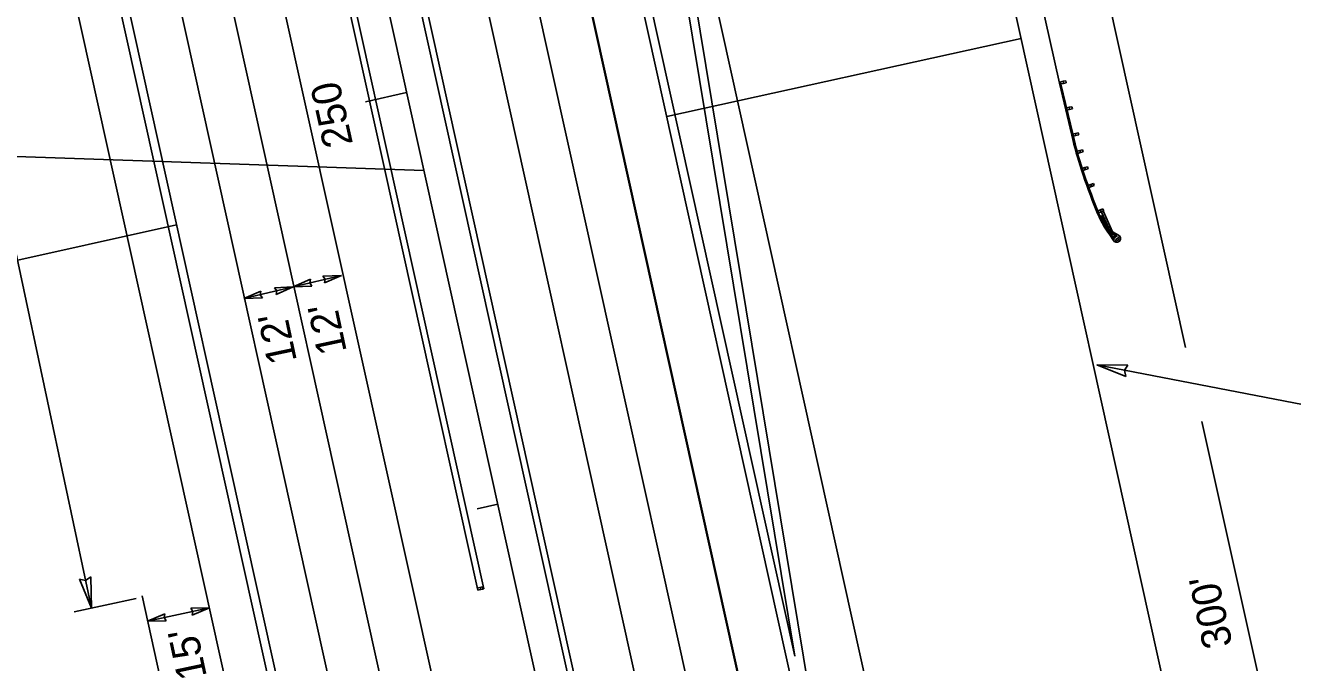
# Model space of a CAD drawing. Extents: x 578088 to 579220, y 1508751 to 1510398.
# Drawn here: x 578333.4 to 578633.8, y 1509907.9 to 1510059 of the extents above; entities that cross this region are included whole.
import ezdxf

# ---------------------------------------------------------------- set-up
doc = ezdxf.new("R2010")
doc.units = 0
for name, color, linetype in [('1', 7, 'Continuous'), ('18', 7, 'Continuous'), ('2', 7, 'Continuous'), ('28', 7, 'Continuous'), ('41', 7, 'Continuous'), ('46', 7, 'Continuous'), ('52', 7, 'Continuous')]:
    doc.layers.add(name, color=color, linetype=linetype)

msp = doc.modelspace()

# ---------------------------------------------------------------- linework, layer by layer
at = {"layer": '1'}
for p, q in [((578639.69, 1509066.69), (578362.17, 1510321.74)), ((578559.88, 1509205.29), (578315.3, 1510311.37))]:
    msp.add_line(p, q, dxfattribs=at)
at = {"layer": '18'}
for p, q in [((578612.63, 1509860.67), (578504, 1510351.92)), ((578545.42, 1509845.81), (578436.79, 1510337.06)), ((578516.77, 1509839.48), (578408.15, 1510330.73)), ((578471.12, 1509495.56), (578291.87, 1510306.19)), ((578415.3, 1510242.58), (578497.77, 1509869.64)), ((578659.48, 1508810.53), (578375.62, 1510094.27)), ((578432.7, 1509599.82), (578361.09, 1509923.69))]:
    msp.add_line(p, q, dxfattribs=at)
at = {"layer": '2'}
for p, q in [((578528.65, 1509842.11), (578420.03, 1510333.36)), ((578515.82, 1509909.43), (578421.98, 1510333.79)), ((578516.94, 1509839.51), (578408.31, 1510330.77)), ((578493.5, 1509834.33), (578384.88, 1510325.58)), ((578482.83, 1509498.15), (578303.59, 1510308.78)), ((578480.88, 1509497.72), (578301.64, 1510308.35)), ((578523.79, 1509873.37), (578484.67, 1510110.52)), ((578515.82, 1509909.43), (578482.71, 1510110.09)), ((578569.45, 1510055.96), (578485.47, 1510037.39)), ((578369.28, 1510011.7), (578294.1, 1509995.07))]:
    msp.add_line(p, q, dxfattribs=at)
at = {"layer": '28'}
for p, q in [((578423.79, 1510043.1), (578414.02, 1510040.94)), ((578445.38, 1509945.46), (578440.49, 1509944.38))]:
    msp.add_line(p, q, dxfattribs=at)
at = {"layer": '41'}
for p, q in [((578612.63, 1509860.67), (578504, 1510351.91)), ((578612.63, 1509860.67), (578504, 1510351.91)), ((578612.63, 1509860.67), (578504, 1510351.91)), ((578671.2, 1508813.02), (578338.64, 1510317))]:
    msp.add_line(p, q, dxfattribs=at)
msp.add_arc((580335.96, 1510415.53), 2083.48, 192.46859, 200.71859, dxfattribs=at)
at = {"layer": '46'}
for p, q in [((578369.74, 1510322.24), (578478.37, 1509830.99)), ((578371.21, 1510322.56), (578479.83, 1509831.31)), ((578440.67, 1509925.07), (578353.63, 1510318.68)), ((578442.13, 1509925.39), (578355.1, 1510319)), ((578578.52, 1510045.32), (578519.21, 1510313.84)), ((578578.52, 1510045.32), (578581.48, 1510032.96)), ((578579.39, 1510045.77), (578578.74, 1510045.62)), ((578578.74, 1510045.62), (578578.85, 1510045.14)), ((578578.79, 1510045.38), (578581.75, 1510033.03)), ((578578.85, 1510045.14), (578579.5, 1510045.28)), ((578580.04, 1510045.91), (578579.39, 1510045.77)), ((578579.39, 1510045.77), (578579.5, 1510045.28)), ((578579.5, 1510045.28), (578580.15, 1510045.42)), ((578580.15, 1510045.42), (578580.04, 1510045.91)), ((578580.84, 1510039.6), (578580.19, 1510039.44)), ((578580.19, 1510039.44), (578580.31, 1510038.96)), ((578580.31, 1510038.96), (578580.95, 1510039.11)), ((578581.48, 1510039.75), (578580.84, 1510039.6)), ((578580.84, 1510039.6), (578580.95, 1510039.11)), ((578580.95, 1510039.11), (578581.6, 1510039.27)), ((578581.6, 1510039.27), (578581.48, 1510039.75)), ((578582.34, 1510033.42), (578581.69, 1510033.27)), ((578581.69, 1510033.27), (578581.81, 1510032.78)), ((578581.81, 1510032.78), (578582.45, 1510032.94)), ((578582.99, 1510033.57), (578582.34, 1510033.42)), ((578582.34, 1510033.42), (578582.45, 1510032.94)), ((578582.45, 1510032.94), (578583.1, 1510033.09)), ((578583.1, 1510033.09), (578582.99, 1510033.57)), ((578583.35, 1510029.34), (578582.71, 1510029.16)), ((578582.71, 1510029.16), (578582.84, 1510028.68)), ((578583.99, 1510029.52), (578583.35, 1510029.34)), ((578583.35, 1510029.34), (578583.49, 1510028.86)), ((578583.49, 1510028.86), (578584.13, 1510029.04)), ((578584.13, 1510029.04), (578583.99, 1510029.52)), ((578582.84, 1510028.68), (578583.49, 1510028.86)), ((578584.57, 1510025.3), (578583.94, 1510025.09)), ((578583.94, 1510025.09), (578584.09, 1510024.62)), ((578584.09, 1510024.62), (578584.73, 1510024.83)), ((578585.2, 1510025.52), (578584.57, 1510025.3)), ((578584.57, 1510025.3), (578584.73, 1510024.83)), ((578584.73, 1510024.83), (578585.36, 1510025.04)), ((578585.36, 1510025.04), (578585.2, 1510025.52)), ((578585.97, 1510021.3), (578585.35, 1510021.07)), ((578585.35, 1510021.07), (578585.52, 1510020.6)), ((578585.52, 1510020.6), (578586.15, 1510020.83)), ((578586.6, 1510021.53), (578585.97, 1510021.3)), ((578585.97, 1510021.3), (578586.15, 1510020.83)), ((578586.15, 1510020.83), (578586.77, 1510021.06)), ((578586.77, 1510021.06), (578586.6, 1510021.53)), ((578587.62, 1510015.05), (578588.81, 1510015.51)), ((578587.79, 1510014.61), (578588.96, 1510015.07)), ((578588.23, 1510015.27), (578588.21, 1510015.27)), ((578588.22, 1510015.28), (578588.39, 1510014.85)), ((578588.38, 1510014.83), (578588.37, 1510014.84)), ((578588.96, 1510015.06), (578588.38, 1510014.83)), ((578590.24, 1510010.9), (578588.45, 1510014.86)), ((578588.81, 1510015.51), (578588.97, 1510015.1)), ((578588.83, 1510015.51), (578588.82, 1510015.5)), ((578588.83, 1510015.51), (578588.99, 1510015.11)), ((578591.14, 1510010.05), (578588.92, 1510015.04)), ((578588.1, 1510013.57), (578588.59, 1510013.8)), ((578588.1, 1510013.57), (578588.68, 1510012.35)), ((578588.56, 1510013.82), (578588.33, 1510013.71)), ((578588.33, 1510013.8), (578588.36, 1510013.74)), ((578588.33, 1510013.71), (578588.34, 1510013.68)), ((578588.46, 1510013.87), (578588.35, 1510013.82)), ((578588.36, 1510013.86), (578588.35, 1510013.85)), ((578588.35, 1510013.85), (578588.36, 1510013.83)), ((578588.53, 1510013.82), (578588.35, 1510013.73)), ((578588.35, 1510013.73), (578588.35, 1510013.72)), ((578588.42, 1510013.89), (578588.36, 1510013.86)), ((578588.38, 1510013.82), (578588.41, 1510013.76)), ((578588.43, 1510013.89), (578588.42, 1510013.89)), ((578588.43, 1510013.89), (578588.44, 1510013.87)), ((578588.44, 1510013.85), (578588.47, 1510013.79)), ((578588.48, 1510013.88), (578588.51, 1510013.81)), ((578588.53, 1510013.81), (578588.53, 1510013.82)), ((578588.57, 1510013.79), (578588.56, 1510013.82)), ((578588.59, 1510013.8), (578589.18, 1510012.59)), ((578588.68, 1510012.35), (578589.18, 1510012.59)), ((578589.03, 1510012.52), (578590.59, 1510010.28)), ((578589.08, 1510012.54), (578590.7, 1510010.24)), ((578589.97, 1510010.61), (578589.96, 1510010.61)), ((578589.97, 1510010.61), (578590.07, 1510010.44)), ((578589.99, 1510010.57), (578590.03, 1510010.59)), ((578590.05, 1510010.57), (578590.01, 1510010.55)), ((578590.07, 1510010.53), (578590.04, 1510010.51)), ((578590.05, 1510010.59), (578590.09, 1510010.52)), ((578590.09, 1510010.5), (578590.05, 1510010.48)), ((578590.06, 1510010.57), (578590.08, 1510010.59)), ((578591.83, 1510009.34), (578590.07, 1510010.44)), ((578590.09, 1510010.58), (578590.08, 1510010.59)), ((578590.1, 1510010.55), (578590.08, 1510010.54)), ((578590.09, 1510010.58), (578590.1, 1510010.56)), ((578590.1, 1510010.56), (578590.1, 1510010.55)), ((578590.48, 1510010.32), (578590.36, 1510010.61)), ((578590.52, 1510010.3), (578590.45, 1510010.48)), ((578590.46, 1510009.33), (578590.53, 1510009.7)), ((578590.46, 1510009.33), (578591.36, 1510008.02)), ((578590.47, 1510009.33), (578590.54, 1510009.7)), ((578590.7, 1510009.49), (578590.47, 1510009.33)), ((578590.47, 1510009.33), (578591.36, 1510008.03)), ((578590.53, 1510010.3), (578590.52, 1510010.31)), ((578590.53, 1510009.7), (578590.54, 1510009.7)), ((578590.91, 1510009.3), (578590.56, 1510010.13)), ((578590.65, 1510009.24), (578590.64, 1510009.26)), ((578590.7, 1510009.49), (578591.25, 1510008.68)), ((578590.7, 1510009.3), (578590.71, 1510009.29)), ((578590.8, 1510009.98), (578590.98, 1510009.72)), ((578591.11, 1510009.44), (578590.85, 1510009.26)), ((578591.39, 1510009.61), (578590.86, 1510009.25)), ((578590.86, 1510009.25), (578591.12, 1510008.86)), ((578591.05, 1510008.64), (578590.9, 1510008.86)), ((578590.94, 1510009.89), (578591.04, 1510009.76)), ((578590.96, 1510008.9), (578591.1, 1510008.69)), ((578591.05, 1510009.76), (578590.98, 1510009.71)), ((578591.11, 1510009.52), (578590.98, 1510009.71)), ((578591.02, 1510009.85), (578591.13, 1510010.05)), ((578591.18, 1510009.57), (578591.05, 1510009.76)), ((578591.08, 1510009.48), (578591.12, 1510009.43)), ((578591.2, 1510009.58), (578591.09, 1510009.51)), ((578591.12, 1510009.51), (578591.16, 1510009.45)), ((578591.12, 1510008.86), (578591.65, 1510009.22)), ((578591.13, 1510010.06), (578592.51, 1510009.27)), ((578591.13, 1510010.05), (578592.5, 1510009.26)), ((578591.17, 1510008.8), (578591.69, 1510009.16)), ((578591.18, 1510009.82), (578591.2, 1510009.81)), ((578591.19, 1510009.56), (578591.23, 1510009.5)), ((578591.23, 1510009.88), (578591.22, 1510009.89)), ((578591.22, 1510009.58), (578591.26, 1510009.52)), ((578591.38, 1510009.62), (578591.25, 1510009.53)), ((578591.25, 1510008.68), (578591.35, 1510008.04)), ((578591.33, 1510009.59), (578591.3, 1510009.68)), ((578591.38, 1510009.62), (578591.5, 1510009.83)), ((578591.69, 1510009.16), (578591.39, 1510009.61)), ((578591.66, 1510009.25), (578591.42, 1510009.59)), ((578591.46, 1510008.93), (578591.43, 1510008.98)), ((578591.5, 1510008.95), (578591.46, 1510009.01)), ((578591.59, 1510009), (578591.49, 1510008.93)), ((578591.51, 1510008.94), (578591.53, 1510008.9)), ((578591.57, 1510009), (578591.53, 1510009.05)), ((578591.53, 1510008.9), (578591.54, 1510008.9)), ((578591.53, 1510008.46), (578591.54, 1510008.44)), ((578591.6, 1510008.94), (578591.54, 1510008.9)), ((578591.6, 1510009.02), (578591.56, 1510009.08)), ((578591.56, 1510008.67), (578591.88, 1510009.02)), ((578591.58, 1510008.99), (578591.6, 1510008.95)), ((578591.59, 1510008.5), (578591.61, 1510008.49)), ((578591.6, 1510009.6), (578591.83, 1510009.47)), ((578591.6, 1510008.95), (578591.6, 1510008.94)), ((578591.86, 1510009.53), (578591.64, 1510009.66)), ((578591.64, 1510009.23), (578591.66, 1510009.25)), ((578591.78, 1510008.09), (578591.79, 1510008.08)), ((578591.84, 1510008.14), (578591.86, 1510008.12)), ((578592.49, 1510009.27), (578591.86, 1510009.32)), ((578591.86, 1510009.32), (578592.51, 1510009.27)), ((578592.05, 1510008.99), (578592.07, 1510008.98)), ((578592.09, 1510009.06), (578592.1, 1510009.05)), ((578592.43, 1510008.77), (578592.45, 1510008.76)), ((578592.47, 1510008.84), (578592.49, 1510008.83)), ((578592.82, 1510008.55), (578592.84, 1510008.54)), ((578592.9, 1510008.07), (578592.82, 1510007.99)), ((578592.86, 1510008.62), (578592.87, 1510008.61)), ((578592.96, 1510008.74), (578592.96, 1510008.64)), ((578592.98, 1510008.28), (578592.97, 1510008.39)), ((578592.98, 1510008.61), (578592.99, 1510008.61)), ((578592.99, 1510008.61), (578592.98, 1510008.61)), ((578592.99, 1510008.42), (578593, 1510008.42)), ((578591.92, 1510007.61), (578592.03, 1510007.62)), ((578592.03, 1510007.73), (578592.04, 1510007.71)), ((578592.05, 1510007.6), (578592.05, 1510007.59)), ((578592.09, 1510007.77), (578592.1, 1510007.75)), ((578592.24, 1510007.61), (578592.24, 1510007.6)), ((578592.24, 1510007.6), (578592.24, 1510007.61)), ((578592.38, 1510007.63), (578592.27, 1510007.64)), ((578592.38, 1510007.63), (578592.27, 1510007.64)), ((578592.58, 1510007.73), (578592.65, 1510007.81)), ((578592.7, 1510007.81), (578592.69, 1510007.82)), ((578592.82, 1510007.95), (578592.82, 1510007.95)), ((578440.67, 1509925.07), (578442.13, 1509925.39))]:
    msp.add_line(p, q, dxfattribs=at)
msp.add_lwpolyline([(578440.91, 1509925.12), (578441.4, 1509925.23), (578441.29, 1509925.72), (578440.8, 1509925.61), (578441.78, 1509925.82), (578441.89, 1509925.34), (578441.4, 1509925.23)], close=True, dxfattribs=at)
msp.add_circle((578592.33, 1510008.28), 0.25, dxfattribs=at)
for centre, radius, start, end in [((578588.68, 1510014.95), 0.0417, 201.0999, 21.0999), ((578588.95, 1510015.1), 0.0423, 291.0999, 21.0999), ((578588.95, 1510015.1), 0.0267, 291.0999, 21.0999), ((578588.36, 1510013.79), 0.0374, 74.4415, 156.8357), ((578588.43, 1510013.79), 0.0674, 85.2687, 146.0085), ((578588.47, 1510013.84), 0.0374, 74.4415, 156.8357), ((578590.03, 1510010.58), 0.0159, 324.0224, 100.1582), ((578590.04, 1510010.54), 0.0335, 346.7631, 77.4175), ((578590.07, 1510010.51), 0.0159, 324.0224, 100.1582), ((578590.67, 1510009.28), 0.0383, 34.2895, 214.2895), ((578590.68, 1510009.26), 0.0383, 214.2895, 34.2895), ((578590.93, 1510008.88), 0.0367, 34.2897, 214.2897), ((578591.07, 1510008.66), 0.0367, 214.2897, 34.2897), ((578591.1, 1510009.49), 0.021, 52.0326, 196.5469), ((578591.12, 1510009.45), 0.0417, 140.9291, 214.2898), ((578591.18, 1510009.48), 0.0719, 87.1554, 161.424), ((578591.2, 1510009.85), 0.0383, 60.29, 240.29), ((578591.21, 1510009.56), 0.021, 52.0326, 196.5469), ((578591.21, 1510009.84), 0.0383, 240.29, 60.29), ((578591.4, 1510008.81), 0.21, 224.1889, 317.2897), ((578592.12, 1510008.47), 0.887, 210.6019, 63.9777), ((578592.12, 1510008.47), 0.877, 210.6019, 63.9777), ((578591.48, 1510008.94), 0.021, 232.0326, 16.5469), ((578591.5, 1510009.02), 0.0719, 267.1554, 341.424), ((578591.56, 1510008.48), 0.0383, 34.2897, 214.2897), ((578591.57, 1510008.46), 0.0383, 214.2897, 34.2897), ((578591.58, 1510009.01), 0.021, 232.0326, 16.5469), ((578591.62, 1510009.63), 0.0367, 60.2897, 240.2897), ((578591.81, 1510008.11), 0.0383, 34.2897, 214.2897), ((578591.82, 1510008.1), 0.0383, 214.2897, 34.2897), ((578591.84, 1510009.5), 0.0367, 240.2897, 60.2897), ((578591.73, 1510009.16), 0.21, 317.2897, 60.2897), ((578592.07, 1510009.03), 0.0383, 60.2897, 240.2897), ((578592.08, 1510009.02), 0.0383, 240.2897, 60.2897), ((578592.45, 1510008.81), 0.0383, 60.2897, 240.2897), ((578592.47, 1510008.8), 0.0383, 240.2897, 60.2897), ((578592.11, 1510008.48), 0.887, 17.2897, 45.3401), ((578592.84, 1510008.59), 0.0383, 60.2897, 240.2897), ((578592.84, 1510007.97), 0.0267, 133.826, 227.2897), ((578592.85, 1510008.58), 0.0383, 240.2897, 60.2897), ((578592.11, 1510008.48), 0.887, 332.2897, 347.2898), ((578592.98, 1510008.64), 0.0267, 178.8261, 272.2898), ((578592.99, 1510008.4), 0.0267, 92.2897, 185.7531), ((578592.11, 1510008.48), 0.887, 356.2474, 8.332), ((578592.11, 1510008.48), 0.887, 229.2393, 257.2897), ((578592.06, 1510007.75), 0.0383, 34.2897, 214.2897), ((578592.03, 1510007.6), 0.0267, 2.2897, 95.7531), ((578592.07, 1510007.73), 0.0383, 214.2897, 34.2897), ((578592.11, 1510008.48), 0.887, 266.2474, 278.332), ((578592.27, 1510007.61), 0.0267, 88.8264, 182.2897), ((578592.27, 1510007.61), 0.0267, 88.826, 182.2897), ((578592.11, 1510008.48), 0.887, 287.2897, 302.2897), ((578592.67, 1510007.8), 0.0267, 47.2897, 140.7535), ((578592.11, 1510008.48), 0.887, 311.2474, 323.3321)]:
    msp.add_arc(centre, radius, start, end, dxfattribs=at)
for centre, major_axis, ratio, start_param, end_param in [((578666.39, 1510052.48), (19.51, -88.21), 0.964395, 4.720359, 4.814544), ((578666.39, 1510052.48), (19.45, -87.94), 0.964286, 4.720359, 4.814544), ((578701.91, 1510064.71), (28.54, -129.04), 0.943102, 4.814552, 4.891815), ((578705.01, 1510065.67), (29.05, -131.35), 0.948697, 4.814552, 4.8899), ((578614, 1510024.97), (-27.84, -6.16), 0.937456, 0.141494, 0.390876), ((578614.23, 1510025.12), (-27.84, -6.16), 0.937456, 0.141494, 0.390876), ((578589.66, 1510003.92), (-3.79, 5.99), 0.813532, 5.382602, 5.555963), ((578589.66, 1510003.92), (-3.78, 5.98), 0.813845, 5.382601, 5.55665)]:
    msp.add_ellipse(centre, major_axis=major_axis, ratio=ratio, start_param=start_param, end_param=end_param, dxfattribs=at)
at = {"layer": '52'}
for p, q in [((578306.96, 1510119.01), (578349.08, 1509920.82)), ((578582.18, 1510101.36), (578608.44, 1509982.6)), ((578246.65, 1510030.8), (578427.87, 1510024.65)), ((578396.93, 1509997.01), (578408.39, 1509999.74)), ((578408.39, 1509999.74), (578403.96, 1509999.55)), ((578403.96, 1509999.55), (578404.48, 1509998.81)), ((578404.35, 1509997.94), (578408.39, 1509999.74)), ((578385.21, 1509994.22), (578396.93, 1509997.01)), ((578389.25, 1509996.01), (578385.21, 1509994.22)), ((578389.12, 1509995.15), (578389.25, 1509996.01)), ((578396.93, 1509997.01), (578392.51, 1509996.82)), ((578392.51, 1509996.82), (578393.02, 1509996.08)), ((578392.89, 1509995.21), (578396.93, 1509997.01)), ((578393.02, 1509996.08), (578392.89, 1509995.21)), ((578400.98, 1509998.8), (578396.93, 1509997.01)), ((578396.93, 1509997.01), (578401.36, 1509997.2)), ((578400.84, 1509997.94), (578400.98, 1509998.8)), ((578401.36, 1509997.2), (578400.84, 1509997.94)), ((578404.48, 1509998.81), (578404.35, 1509997.94)), ((578385.21, 1509994.22), (578389.63, 1509994.41)), ((578389.63, 1509994.41), (578389.12, 1509995.15)), ((578587.4, 1509978.51), (578594.25, 1509975.76)), ((578594.77, 1509978.46), (578587.4, 1509978.51)), ((578587.4, 1509978.5), (578686.84, 1509959.31)), ((578593.98, 1509977.24), (578594.77, 1509978.46)), ((578594.25, 1509975.76), (578593.98, 1509977.24)), ((578612.31, 1509965.1), (578646.95, 1509808.43)), ((578347.69, 1509927.38), (578346.26, 1509927.64)), ((578346.26, 1509927.64), (578349.08, 1509920.82)), ((578348.95, 1509928.21), (578347.69, 1509927.38)), ((578349.08, 1509920.82), (578348.95, 1509928.21)), ((578359.69, 1509923.08), (578345.02, 1509919.96)), ((578377.08, 1509920.86), (578362.4, 1509917.74)), ((578366.49, 1509919.44), (578362.4, 1509917.74)), ((578366.34, 1509918.57), (578366.49, 1509919.44)), ((578366.83, 1509917.82), (578366.34, 1509918.57)), ((578377.08, 1509920.86), (578372.65, 1509920.78)), ((578372.65, 1509920.78), (578373.14, 1509920.02)), ((578372.99, 1509919.16), (578377.08, 1509920.86)), ((578373.14, 1509920.02), (578372.99, 1509919.16)), ((578362.4, 1509917.74), (578366.83, 1509917.82))]:
    msp.add_line(p, q, dxfattribs=at)

# ---------------------------------------------------------------- texts
at = {"layer": '28'}
msp.add_text('250', height=7, rotation=102.4686, dxfattribs=at).set_placement((578411.11, 1510030.94))
at = {"layer": '52'}
for s, p in [("12'", (578409.65, 1509981.69)), ("12'", (578397.83, 1509979.47)), ("300'", (578619.6, 1509912.06)), ("15'", (578376.49, 1509904.59))]:
    msp.add_text(s, height=7, rotation=102, dxfattribs=at).set_placement(p)

doc.saveas('drawing.dxf')
